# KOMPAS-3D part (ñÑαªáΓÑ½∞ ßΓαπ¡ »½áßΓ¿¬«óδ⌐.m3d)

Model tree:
1. Эскиз:1
2. Операция выдавливания:1
     Расстояние 1 = 30
3. Эскиз:2
4. Операция выдавливания:2
     Расстояние 1 = 20; Расстояние 2 = 30
5. Скругление:1
     Радиус = 3
6. Эскиз:3
7. Вырезать элемент выдавливания:1
     Расстояние 1 = 20
8. Эскиз:4
9. Вырезать элемент выдавливания:2
     Расстояние 1 = 4; Угол 1 = 32
10. Эскиз:5
11. Вырезать элемент выдавливания:3
     Расстояние 2 = 20; Расстояние 1 = 94
